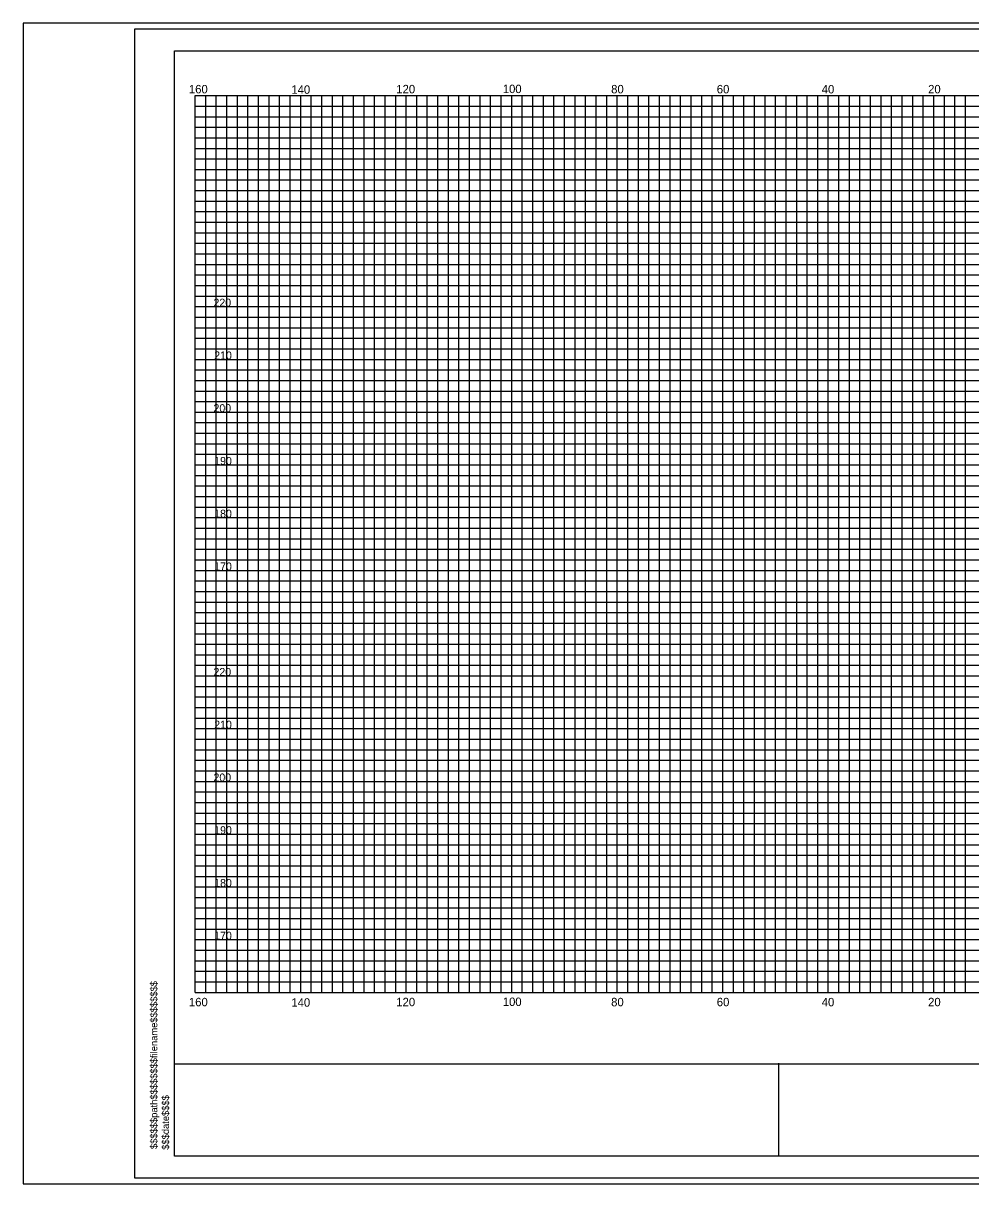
# Model space of a CAD drawing. Extents: x 967 to 1326, y 964 to 3144.
# Drawn here: x 967.4 to 1147, y 1803.7 to 2023.7 of the extents above; entities that cross this region are included whole.
import ezdxf

# ---------------------------------------------------------------- set-up
doc = ezdxf.new("R2010")
doc.units = 0
for name, color, linetype in [('Default', 7, 'Continuous'), ('RD_GPK_XS_Cell', 7, 'Continuous'), ('RD_XS_ExGround', 7, 'Continuous'), ('RD_XS_ExPaveRet', 7, 'Continuous'), ('RD_XS_Misc_Line', 7, 'Continuous'), ('RD_XS_TX_Elev_EX', 7, 'Continuous'), ('RD_XS_TX_Station', 7, 'Continuous')]:
    doc.layers.add(name, color=color, linetype=linetype)

msp = doc.modelspace()

# ---------------------------------------------------------------- linework, layer by layer
at = {"layer": 'RD_GPK_XS_Cell'}
for p, q in [((1000, 2010), (1320, 2010)), ((1000, 1840), (1000, 2010)), ((1010, 1840), (1010, 2010)), ((1020, 1840), (1020, 2010)), ((1030, 1840), (1030, 2010)), ((1040, 1840), (1040, 2010)), ((1050, 1840), (1050, 2010)), ((1060, 1840), (1060, 2010)), ((1070, 1840), (1070, 2010)), ((1080, 1840), (1080, 2010)), ((1090, 1840), (1090, 2010)), ((1100, 1840), (1100, 2010)), ((1110, 1840), (1110, 2010)), ((1120, 1840), (1120, 2010)), ((1130, 1840), (1130, 2010)), ((1140, 1840), (1140, 2010)), ((1000, 2000), (1320, 2000)), ((1000, 1990), (1320, 1990)), ((1000, 1980), (1320, 1980)), ((1000, 1970), (1320, 1970)), ((1000, 1960), (1320, 1960)), ((1000, 1950), (1320, 1950)), ((1000, 1940), (1320, 1940)), ((1000, 1930), (1320, 1930)), ((1000, 1920), (1320, 1920)), ((1000, 1910), (1320, 1910)), ((1000, 1900), (1320, 1900)), ((1000, 1890), (1320, 1890)), ((1000, 1880), (1320, 1880)), ((1000, 1870), (1320, 1870)), ((1000, 1860), (1320, 1860)), ((1000, 1850), (1320, 1850)), ((1000, 1840), (1320, 1840))]:
    msp.add_line(p, q, dxfattribs=at)
at = {"layer": 'RD_XS_ExGround'}
for p, q in [((1002, 1840), (1002, 2010)), ((1004, 1840), (1004, 2010)), ((1006, 1840), (1006, 2010)), ((1008, 1840), (1008, 2010)), ((1012, 1840), (1012, 2010)), ((1014, 1840), (1014, 2010)), ((1016, 1840), (1016, 2010)), ((1018, 1840), (1018, 2010)), ((1022, 1840), (1022, 2010)), ((1024, 1840), (1024, 2010)), ((1026, 1840), (1026, 2010)), ((1028, 1840), (1028, 2010)), ((1032, 1840), (1032, 2010)), ((1034, 1840), (1034, 2010)), ((1036, 1840), (1036, 2010)), ((1038, 1840), (1038, 2010)), ((1042, 1840), (1042, 2010)), ((1044, 1840), (1044, 2010)), ((1046, 1840), (1046, 2010)), ((1048, 1840), (1048, 2010)), ((1052, 1840), (1052, 2010)), ((1054, 1840), (1054, 2010)), ((1056, 1840), (1056, 2010)), ((1058, 1840), (1058, 2010)), ((1062, 1840), (1062, 2010)), ((1064, 1840), (1064, 2010)), ((1066, 1840), (1066, 2010)), ((1068, 1840), (1068, 2010)), ((1072, 1840), (1072, 2010)), ((1074, 1840), (1074, 2010)), ((1076, 1840), (1076, 2010)), ((1078, 1840), (1078, 2010)), ((1082, 1840), (1082, 2010)), ((1084, 1840), (1084, 2010)), ((1086, 1840), (1086, 2010)), ((1088, 1840), (1088, 2010)), ((1092, 1840), (1092, 2010)), ((1094, 1840), (1094, 2010)), ((1096, 1840), (1096, 2010)), ((1098, 1840), (1098, 2010)), ((1102, 1840), (1102, 2010)), ((1104, 1840), (1104, 2010)), ((1106, 1840), (1106, 2010)), ((1108, 1840), (1108, 2010)), ((1112, 1840), (1112, 2010)), ((1114, 1840), (1114, 2010)), ((1116, 1840), (1116, 2010)), ((1118, 1840), (1118, 2010)), ((1122, 1840), (1122, 2010)), ((1124, 1840), (1124, 2010)), ((1126, 1840), (1126, 2010)), ((1128, 1840), (1128, 2010)), ((1132, 1840), (1132, 2010)), ((1134, 1840), (1134, 2010)), ((1136, 1840), (1136, 2010)), ((1138, 1840), (1138, 2010)), ((1142, 1840), (1142, 2010)), ((1144, 1840), (1144, 2010)), ((1146, 1840), (1146, 2010)), ((1000, 2008), (1320, 2008)), ((1000, 2006), (1320, 2006)), ((1000, 2004), (1320, 2004)), ((1000, 2002), (1320, 2002)), ((1000, 1998), (1320, 1998)), ((1000, 1996), (1320, 1996)), ((1000, 1994), (1320, 1994)), ((1000, 1992), (1320, 1992)), ((1000, 1988), (1320, 1988)), ((1000, 1986), (1320, 1986)), ((1000, 1984), (1320, 1984)), ((1000, 1982), (1320, 1982)), ((1000, 1978), (1320, 1978)), ((1000, 1976), (1320, 1976)), ((1000, 1974), (1320, 1974)), ((1000, 1972), (1320, 1972)), ((1000, 1968), (1320, 1968)), ((1000, 1966), (1320, 1966)), ((1000, 1964), (1320, 1964)), ((1000, 1962), (1320, 1962)), ((1000, 1958), (1320, 1958)), ((1000, 1956), (1320, 1956)), ((1000, 1954), (1320, 1954)), ((1000, 1952), (1320, 1952)), ((1000, 1948), (1320, 1948)), ((1000, 1946), (1320, 1946)), ((1000, 1944), (1320, 1944)), ((1000, 1942), (1320, 1942)), ((1000, 1938), (1320, 1938)), ((1000, 1936), (1320, 1936)), ((1000, 1934), (1320, 1934)), ((1000, 1932), (1320, 1932)), ((1000, 1928), (1320, 1928)), ((1000, 1926), (1320, 1926)), ((1000, 1924), (1320, 1924)), ((1000, 1922), (1320, 1922)), ((1000, 1918), (1320, 1918)), ((1000, 1916), (1320, 1916)), ((1000, 1914), (1320, 1914)), ((1000, 1912), (1320, 1912)), ((1000, 1908), (1320, 1908)), ((1000, 1906), (1320, 1906)), ((1000, 1904), (1320, 1904)), ((1000, 1902), (1320, 1902)), ((1000, 1898), (1320, 1898)), ((1000, 1896), (1320, 1896)), ((1000, 1894), (1320, 1894)), ((1000, 1892), (1320, 1892)), ((1000, 1888), (1320, 1888)), ((1000, 1886), (1320, 1886)), ((1000, 1884), (1320, 1884)), ((1000, 1882), (1320, 1882)), ((1000, 1878), (1320, 1878)), ((1000, 1876), (1320, 1876)), ((1000, 1874), (1320, 1874)), ((1000, 1872), (1320, 1872)), ((1000, 1868), (1320, 1868)), ((1000, 1866), (1320, 1866)), ((1000, 1864), (1320, 1864)), ((1000, 1862), (1320, 1862)), ((1000, 1858), (1320, 1858)), ((1000, 1856), (1320, 1856)), ((1000, 1854), (1320, 1854)), ((1000, 1852), (1320, 1852)), ((1000, 1848), (1320, 1848)), ((1000, 1846), (1320, 1846)), ((1000, 1844), (1320, 1844)), ((1000, 1842), (1320, 1842))]:
    msp.add_line(p, q, dxfattribs=at)
at = {"layer": 'RD_XS_ExPaveRet'}
for points in [[(967.41, 1803.72), (1326.28, 1803.72), (1326.28, 2023.72), (967.41, 2023.72)], [(988.52, 1804.84), (1326.28, 1804.84), (1326.28, 2022.6), (988.52, 2022.6)]]:
    msp.add_lwpolyline(points, close=True, dxfattribs=at)
at = {"layer": 'RD_XS_TX_Elev_EX'}
for p, q in [((996.11, 1808.98), (996.11, 2018.46)), ((996.11, 2018.46), (1323.89, 2018.46)), ((996.11, 1826.49), (1323.89, 1826.49)), ((1110.59, 1808.98), (1110.59, 1826.56)), ((1323.89, 1808.98), (996.11, 1808.98))]:
    msp.add_line(p, q, dxfattribs=at)
at = {"layer": 'RD_XS_TX_Station'}
msp.add_lwpolyline([(967.41, 1803.72), (1326.28, 1803.72), (1326.28, 2023.72), (967.41, 2023.72)], close=True, dxfattribs=at)

# ---------------------------------------------------------------- texts
at = {"layer": 'Default'}
for s, p in [('220', (1003.47, 1970)), ('210', (1003.61, 1960)), ('200', (1003.47, 1950)), ('190', (1003.61, 1940)), ('180', (1003.61, 1930)), ('170', (1003.61, 1920)), ('220', (1003.47, 1900)), ('210', (1003.61, 1890)), ('200', (1003.47, 1880)), ('190', (1003.61, 1870)), ('180', (1003.61, 1860)), ('170', (1003.61, 1850))]:
    msp.add_text(s, height=1.5, dxfattribs=at).set_placement(p)
for s, p in [('$$$$$$path$$$$$$$$filename$$$$$$$$', (992.83, 1810.31)), ('$$$date$$$$', (995.04, 1810.17))]:
    msp.add_text(s, height=1.3258, rotation=90, dxfattribs=at).set_placement(p)
at = {"layer": 'RD_XS_Misc_Line'}
for s, p in [('160', (998.81, 2010.42)), ('140', (1018.23, 2010.34)), ('120', (1038.12, 2010.43)), ('100', (1058.3, 2010.47)), ('80', (1078.84, 2010.42)), ('60', (1098.86, 2010.42)), ('40', (1118.75, 2010.41)), ('20', (1138.91, 2010.42)), ('160', (998.81, 1837.37)), ('140', (1018.23, 1837.29)), ('120', (1038.12, 1837.38)), ('100', (1058.3, 1837.42)), ('80', (1078.84, 1837.37)), ('60', (1098.86, 1837.37)), ('40', (1118.75, 1837.36)), ('20', (1138.91, 1837.37))]:
    msp.add_text(s, height=1.6, dxfattribs=at).set_placement(p)

doc.saveas('drawing.dxf')
